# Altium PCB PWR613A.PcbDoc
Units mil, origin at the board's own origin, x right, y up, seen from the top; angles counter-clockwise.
Board outline 2500 x 1850 mil, 2 copper layers (Top Layer, Bottom Layer), stack 64.8 mil thick; 109 components, 70 nets, 324 pads, 62 vias.
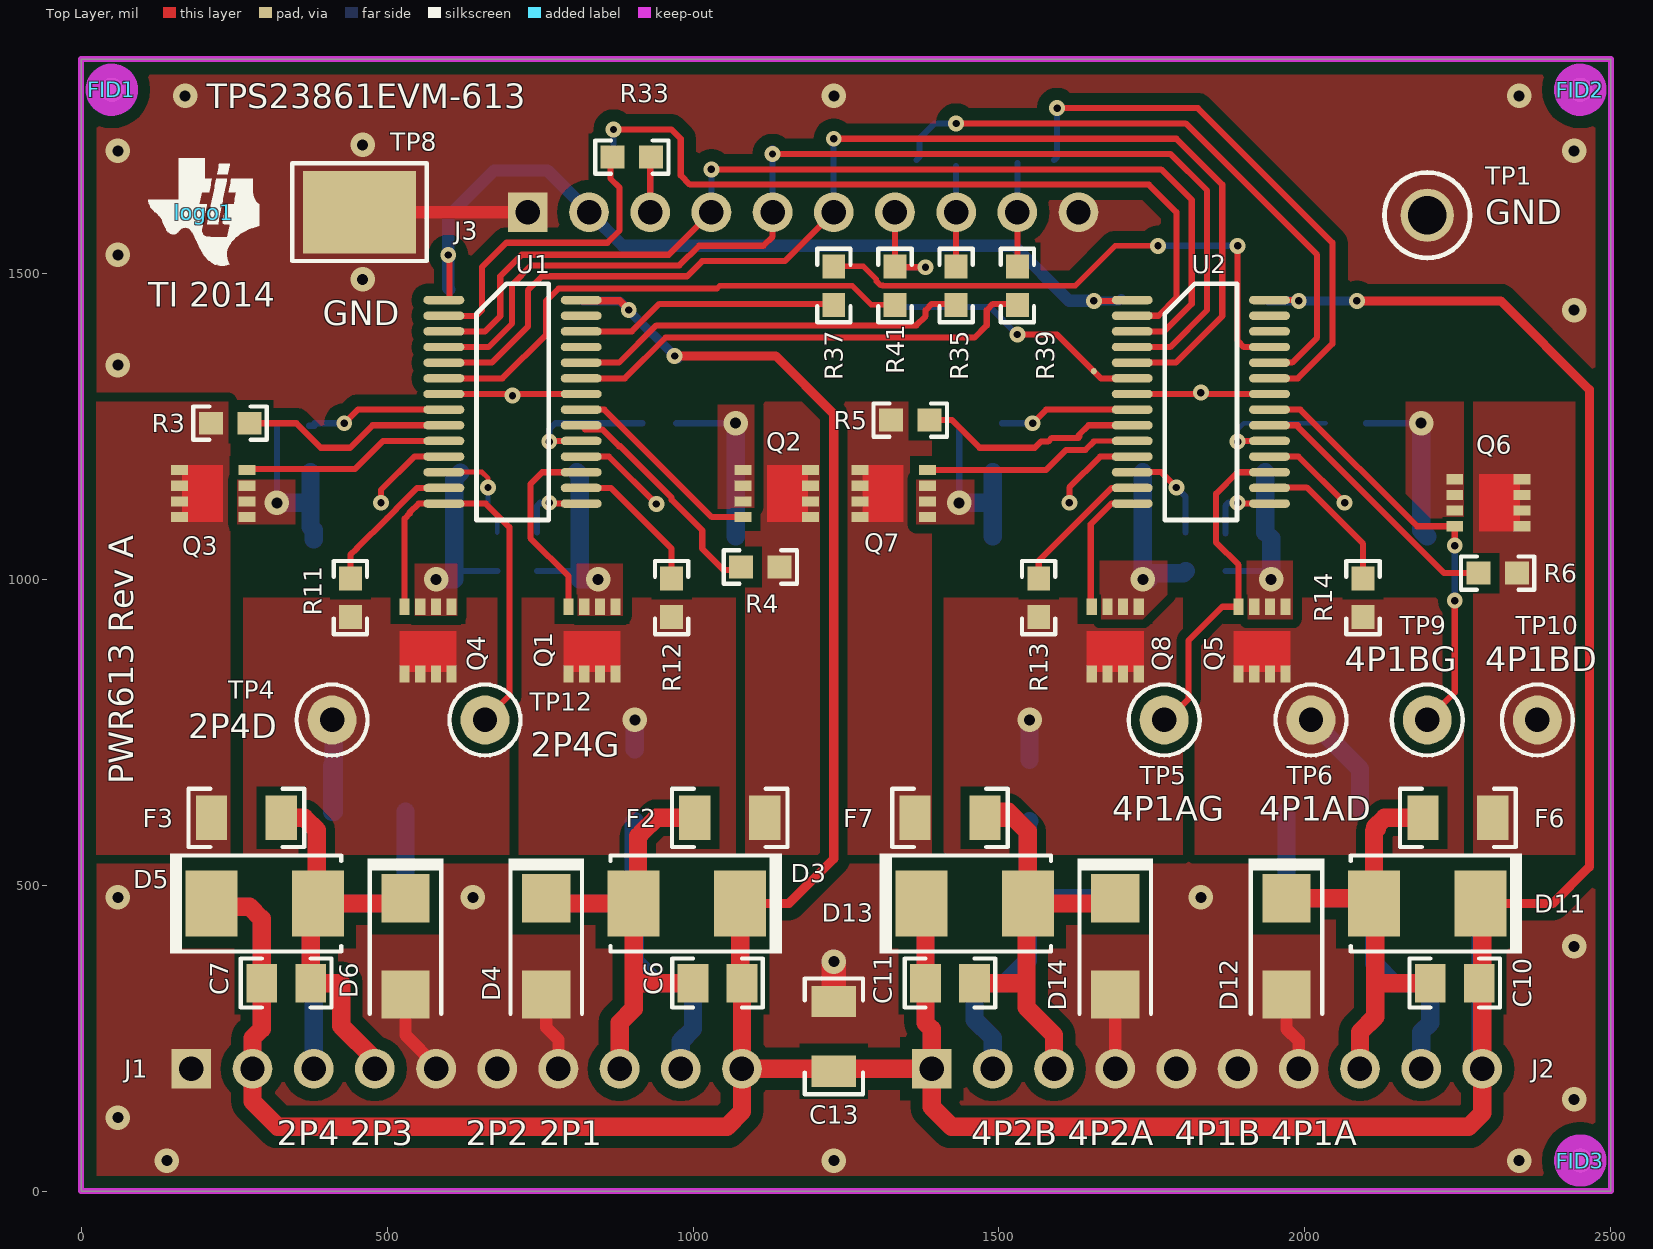
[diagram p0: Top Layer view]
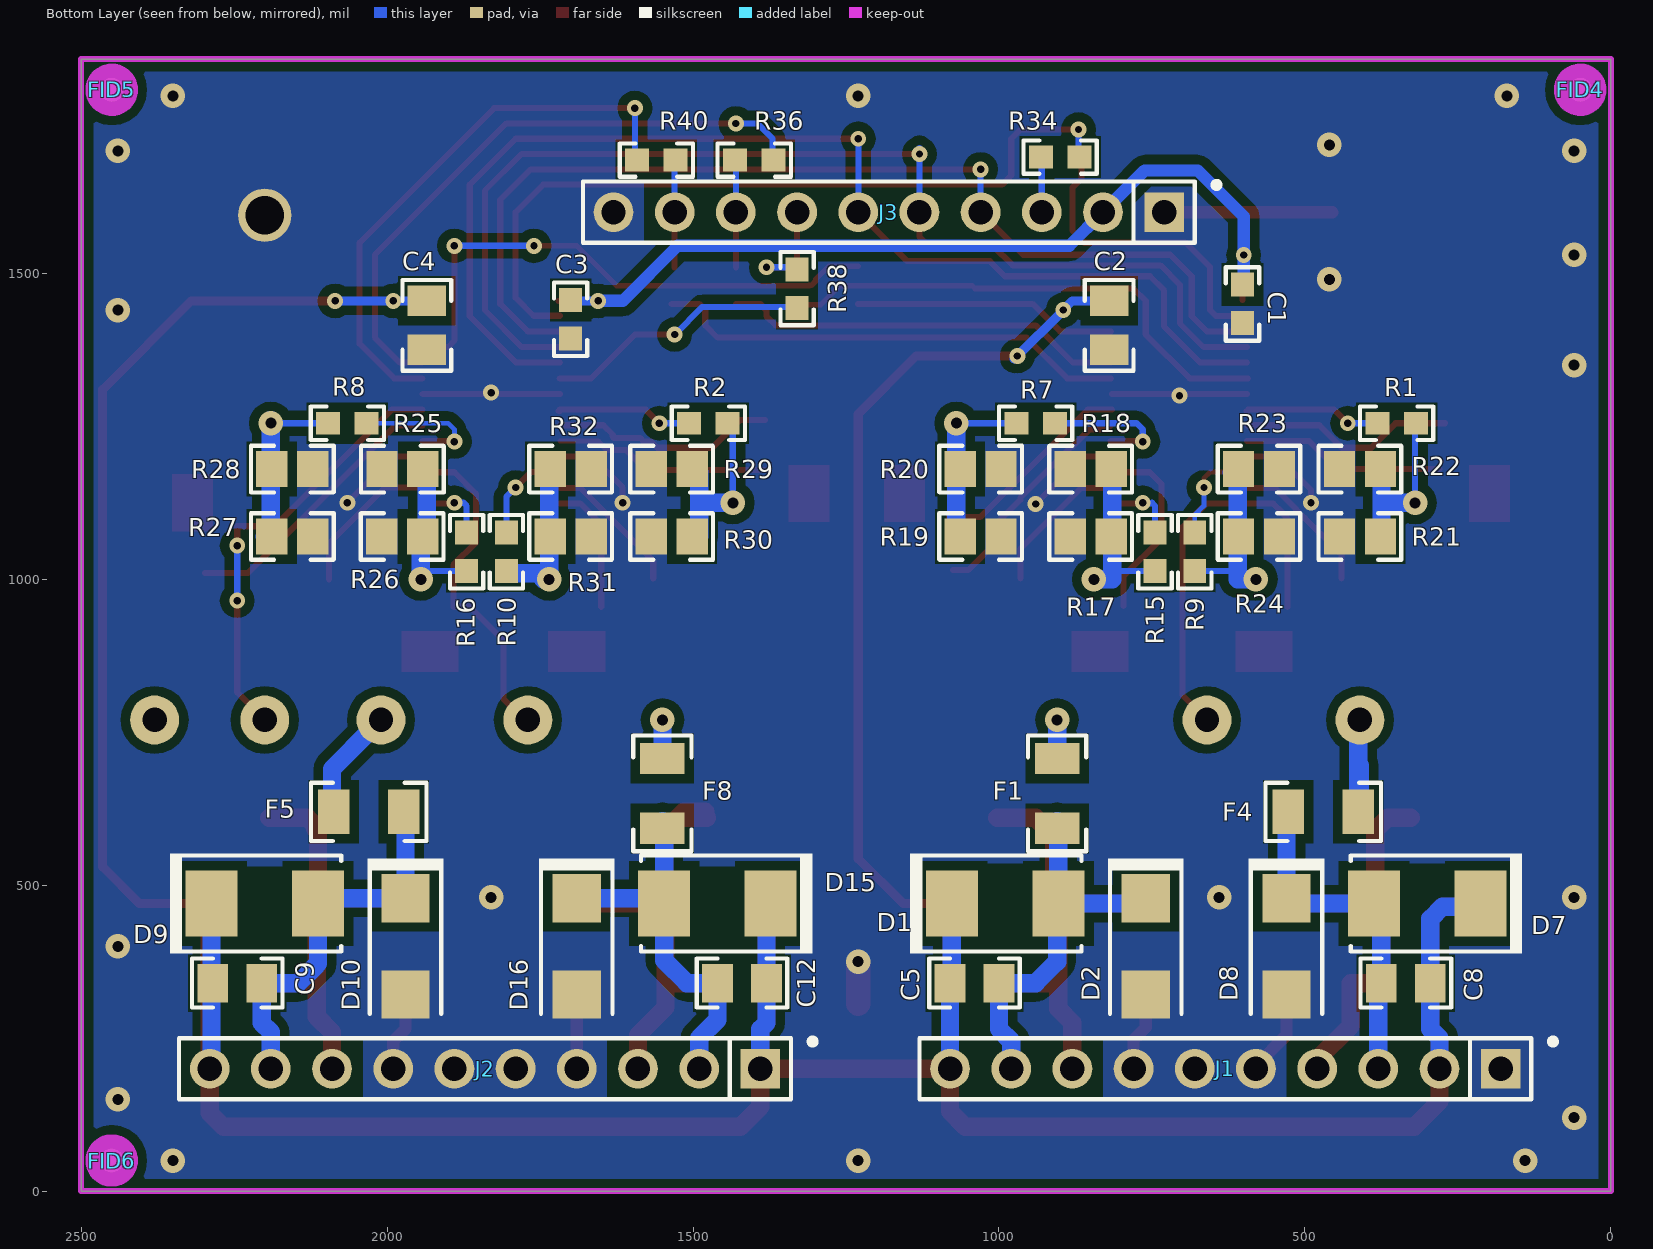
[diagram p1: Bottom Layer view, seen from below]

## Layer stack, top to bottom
Top Layer: signal copper 2.8
Dielectric: core 59.2, FR-4, Dk 4.8
Bottom Layer: signal copper 2.8

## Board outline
0,0 0,1850 2500,1850 2500,0 0,0

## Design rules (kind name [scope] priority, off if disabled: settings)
AcuteAngle [All] p1: minimum=4.50000000000000E+0001 checktracksonly=FALSE
AssemblyTestPointUsage [All] p1: valid=2
Clearance Clearance_19 [InNamedPolygon('PSE-D4')] p1: gap=15
Clearance Clearance_18 [InNamedPolygon('PSE-D7')] p2: gap=15
Clearance Clearance_17 [InNamedPolygon('PSE-D6')] p3: gap=15
Clearance Clearance_16 [InNamedPolygon('PSE-D5')] p4: gap=15
Clearance Clearance_13 [InNamedPolygon('PSE-D1')] p5: gap=15
Clearance Clearance_12 [InNamedPolygon('PSE-D0')] p6: gap=15
Clearance Clearance_11 [InNamedPolygon('PSE-D3')] p7: gap=15
Clearance Clearance_10 [InNamedPolygon('PSE-D2')] p8: gap=15
Clearance Clearance_1 [InNamedPolygon('GND-Bottom')] p9: gap=15
Clearance Clearance_2 [InNamedPolygon('GND-Top')] p10: gap=20
Clearance Clearance_BoardEdge_MountingHoles [OnCopper and InComponentClass('Mounting Holes') vs IsKeepOut] p11: gap=40
Clearance Clearance_BoardEdge_Poly [OnCopper and InPoly vs IsKeepOut] p12: gap=15
Clearance Clearance_BoardEdge [OnCopper and InPoly vs IsKeepOut] p13: gap=25
Clearance [All] p14: gap=7
ComponentClearance ComponentClearance_Logo [All] p1: gap=0 collisioncheckmode=3 verticalgap=10 showdistances=FALSE
ComponentClearance ComponentClearance_ScrewToNut [(HasFootprint('NY PMS 440 0025 PH')) vs (HasFootprint('Keystone_1902C'))] p2: gap=5 collisioncheckmode=3 verticalgap=10 showdistances=FALSE
ComponentClearance ComponentClearance_MountingHoles [InComponentClass('Mounting Holes')] p3: gap=250 collisioncheckmode=3 verticalgap=100000 showdistances=FALSE
ComponentClearance ComponentClearance_SmallPassives [HasFootprint('0201*') or HasFootprint('0402*') or HasFootprint('0508') or HasFootprint('0603*') or HasFootprint('0612') or HasFootprint('0805*') or HasFootprint('0815*') or HasFootprint('0830*') or HasFootprint('1206*') or HasFootprint('1210*') or HasFootprint('1808*') or HasFootprint('1812*') or HasFootprint('1825*') or HasFootprint('2010*') or HasFootprint('2220*') or HasFootprint('2225*') or HasFootprint('2512*') or HasFootprint('2728*') or HasFootprint('3518*') vs HasFootprint('0201*') or HasFootprint('0402*') or HasFootprint('0508') or HasFootprint('0603*') or HasFootprint('0612') or HasFootprint('0805*') or HasFootprint('0815*') or HasFootprint('0830*') or HasFootprint('1206*') or HasFootprint('1210*') or HasFootprint('1808*') or HasFootprint('1812*') or HasFootprint('1825*') or HasFootprint('2010*') or HasFootprint('2220*') or HasFootprint('2225*') or HasFootprint('2512*') or HasFootprint('2728*') or HasFootprint('3518*')] p4: gap=10 collisioncheckmode=3 verticalgap=10 showdistances=FALSE
ComponentClearance ComponentClearance_THtoSMT [IsThruComponent vs IsSMTComponent] p5: gap=10 collisioncheckmode=3 verticalgap=100000 showdistances=FALSE
ComponentClearance ComponentClearance_THtoTH [IsThruComponent vs IsThruComponent] p6: gap=80 collisioncheckmode=3 verticalgap=100000 showdistances=FALSE
ComponentClearance [All] p7: gap=10 collisioncheckmode=3 verticalgap=10 showdistances=FALSE
DiffPairsRouting [All] p1: maxlimit=100 minlimit=10 mostfreqgap=10 maxuncoupledlength=1000
FabricationTestPointUsage TestPointUsage [All] p1: valid=2 allowmultiple=FALSE
FabricationTestpoint Testpoint [All] p1: side=3 testpointundercomponent=TRUE minsize=40 maxsize=100 preferedsize=60 minholesize=0 maxholesize=40 preferedholesize=32 testpointgrid=1 allowsidetop=TRUE allowsidebottom=TRUE usegrid=TRUE gridtolerance=0.01
FanoutControl Fanout_LCC [IsLCC] p1: bgadir=Out bgaviamode=Centered fanoutstyle=Auto fanoutdirection=Alternating viagrid=1 // Fanout_LCC (Default Rule)
FanoutControl Fanout_BGA [IsBGA] p2: bgadir=Out bgaviamode=Centered fanoutstyle=Auto fanoutdirection=Alternating viagrid=1 // Fanout_BGA (Default Rule)
FanoutControl Fanout_Default [All] p4: bgadir=Out bgaviamode=Centered fanoutstyle=Auto fanoutdirection=Alternating viagrid=1 // Fanout_Default (Default Rule)
FanoutControl Fanout_Small [(CompPinCount < 5)] p5: bgadir=Out bgaviamode=Centered fanoutstyle=Auto fanoutdirection=OutThenIn viagrid=1 // Fanout_Small (Default Rule)
HoleSize [All] p1: absolutevalues=TRUE maxlimit=251 minlimit=7 maxpercent=80.000 minpercent=20.000
MinimumAnnularRing [All] p1: minimumring=5
MinimumSolderMaskSliver MinimumSolderMaskSliver_Logo [InComponentClass('Logo') vs InComponentClass('Logo')] p1: minsoldermaskwidth=0.7
MinimumSolderMaskSliver [All] p2: minsoldermaskwidth=4
PlaneConnect [All] p1: planeconnectstyle=Direct reliefexpansion=10 reliefentries=4 reliefconductorwidth=10 reliefairgap=10
PolygonConnect [All] p1: connectstyle=Direct reliefconductorwidth=10 reliefentries=4 polygonreliefangle="90 Angle" airgapwidth=10
RoutingVias [All] p1: holewidth=16 width=34 viastyle="Through Hole" minholewidth=7 minwidth=18 maxholewidth=40 maxwidth=65
SMDToCorner [All] p1: distance=20000
SilkToSilkClearance [All] p1: silktosilkclearance=5
SilkscreenOverComponentPads [All] p1: minsilkscreentomaskgap=5
SolderMaskExpansion [All] p1: expansion=3
Width [All] p1: maxlimit=100 minlimit=6 preferedwidth=10 checkconnectedcopper=TRUE
14 further rules are at their usual default settings.

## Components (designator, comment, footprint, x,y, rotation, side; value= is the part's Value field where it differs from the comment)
C1 "06035C104KAT2A" 0603 602,1450 r270 bottom
C2 "C2012X7R2A104K" 0805_HV 820,1415 r270 bottom
C3 "06035C104KAT2A" 0603 1700,1425 r270 bottom
C4 "C2012X7R2A104K" 0805_HV 1935,1415 r270 bottom
C5 "C2012X7R2A104K" 0805_HV 1040,340 r180 bottom
C6 "C2012X7R2A104K" 0805_HV 1040,340 r180 top
C7 "C2012X7R2A104K" 0805_HV 335,340 r0 top
C8 "C2012X7R2A104K" 0805_HV 335,340 r0 bottom
C9 "C2012X7R2A104K" 0805_HV 2245,340 r180 bottom
C10 "C2012X7R2A104K" 0805_HV 2245,340 r180 top
C11 "C2012X7R2A104K" 0805_HV 1420,340 r0 top
C12 "C2012X7R2A104K" 0805_HV 1420,340 r0 bottom
C13 "GRM31CR72A105KA01L" 1206 1230,252.83 r90 top
D1 "SMBJ58A-13-F" SMB 990,470 r180 bottom
D2 "10MQ100NTRPBF" SMA 760,400 r270 bottom
D3 "SMBJ58A-13-F" SMB 990,470 r180 top
D4 "10MQ100NTRPBF" SMA 760,400 r270 top
D5 "SMBJ58A-13-F" SMB 300,469.98 r0 top
D6 "10MQ100NTRPBF" SMA 530,399.98 r270 top
D7 "SMBJ58A-13-F" SMB 300,469.98 r0 bottom
D8 "10MQ100NTRPBF" SMA 530,399.98 r270 bottom
D9 "SMBJ58A-13-F" SMB 2200,470 r180 bottom
D10 "10MQ100NTRPBF" SMA 1969.99,399.99 r270 bottom
D11 "SMBJ58A-13-F" SMB 2200,470 r180 top
D12 "10MQ100NTRPBF" SMA 1969.99,399.99 r270 top
D13 "SMBJ58A-13-F" SMB 1460.12,469.98 r0 top
D14 "10MQ100NTRPBF" SMA 1690.12,399.98 r270 top
D15 "SMBJ58A-13-F" SMB 1460.12,469.98 r0 bottom
D16 "10MQ100NTRPBF" SMA 1690.12,399.98 r270 bottom
F1 "C1S 1.5" 1206 905,650 r90 bottom
F2 "C1S 1.5" 1206 1060,610 r0 top
F3 "C1S 1.5" 1206 270,610 r180 top
F4 "C1S 1.5" 1206 470,619.98 r180 bottom
F5 "C1S 1.5" 1206 2030,619.86 r0 bottom
F6 "C1S 1.5" 1206 2250,610 r0 top
F7 "C1S 1.5" 1206 1420,610 r180 top
F8 "C1S 1.5" 1206 1550,650 r90 bottom
FID1 "Fiducial" Fiducial10-20 50,1800 r90 top
FID2 "Fiducial" Fiducial10-20 2450,1800 r90 top
FID3 "Fiducial" Fiducial10-20 2450,50 r90 top
FID4 "Fiducial" Fiducial10-20 50,1800 r90 bottom
FID5 "Fiducial" Fiducial10-20 2450,1800 r90 bottom
FID6 "Fiducial" Fiducial10-20 2450,50 r90 bottom
J1 "2P4 2P3 2P2 2P1" TSW-110-07-G-S 630,200 r0 bottom
J2 "Port8&7&6&5" TSW-110-07-G-S 1840,200 r0 bottom
J3 "TSW-110-07-G-S" TSW-110-07-G-S 1180,1600 r0 bottom
logo1 "Texas Instruments" TI_Symbol_Overlay_Small 200,1600 r0 top (schematic designator Logo1)
Q1 "FDMC3612" TRANS_Fairchild_MLP08T 835,900 r270 top
Q2 "FDMC3612" TRANS_Fairchild_MLP08T 1136.68,1140 r0 top
Q3 "FDMC3612" TRANS_Fairchild_MLP08T 215.92,1140 r180 top
Q4 "FDMC3612" TRANS_Fairchild_MLP08T 567,900 r270 top
Q5 "FDMC3612" TRANS_Fairchild_MLP08T 1930,900 r270 top
Q6 "FDMC3612" TRANS_Fairchild_MLP08T 2300,1125 r0 top
Q7 "FDMC3612" TRANS_Fairchild_MLP08T 1327.95,1140 r180 top
Q8 "FDMC3612" TRANS_Fairchild_MLP08T 1690,900 r270 top
R1 "CRCW060322R1FKEA" 0603 350,1255 r0 bottom
R2 "CRCW060322R1FKEA" 0603 1475,1255 r0 bottom
R3 "CRCW060347R0JNEA" 0603 243.35,1255 r0 top
R4 "CRCW060347R0JNEA" 0603 1110,1020 r0 top
R5 "CRCW060347R0JNEA" 0603 1355,1260 r0 top
R6 "CRCW060347R0JNEA" 0603 2315,1010 r0 top
R7 "CRCW060322R1FKEA" 0603 940,1255 r0 bottom
R8 "CRCW060322R1FKEA" 0603 2065,1255 r0 bottom
R9 "CRCW060322R1FKEA" 0603 680,1045 r90 bottom
R10 "CRCW060322R1FKEA" 0603 1805,1045 r90 bottom
R11 "CRCW060347R0JNEA" 0603 440,970 r90 top
R12 "CRCW060347R0JNEA" 0603 965,970 r270 top
R13 "CRCW060347R0JNEA" 0603 1565,970 r90 top
R14 "CRCW060347R0JNEA" 0603 2095,970 r270 top
R15 "CRCW060322R1FKEA" 0603 745,1045 r270 bottom
R16 "CRCW060322R1FKEA" 0603 1870,1045 r270 bottom
R17 "CRM0805-FX-R510ELF" 0805 850,1070 r180 bottom
R18 "CRM0805-FX-R510ELF" 0805 850,1180 r180 bottom
R19 "CRM0805-FX-R510ELF" 0805 1030,1070 r0 bottom
R20 "CRM0805-FX-R510ELF" 0805 1030,1180 r0 bottom
R21 "CRM0805-FX-R510ELF" 0805 410,1070 r180 bottom
R22 "CRM0805-FX-R510ELF" 0805 410,1180 r180 bottom
R23 "CRM0805-FX-R510ELF" 0805 575,1180 r0 bottom
R24 "CRM0805-FX-R510ELF" 0805 575,1070 r0 bottom
R25 "CRM0805-FX-R510ELF" 0805 1975,1180 r180 bottom
R26 "CRM0805-FX-R510ELF" 0805 1975.34,1070 r180 bottom
R27 "CRM0805-FX-R510ELF" 0805 2155,1070 r0 bottom
R28 "CRM0805-FX-R510ELF" 0805 2155,1180 r0 bottom
R29 "CRM0805-FX-R510ELF" 0805 1535,1180 r180 bottom
R30 "CRM0805-FX-R510ELF" 0805 1535,1070 r180 bottom
R31 "CRM0805-FX-R510ELF" 0805 1700,1070 r0 bottom
R32 "CRM0805-FX-R510ELF" 0805 1700,1180 r0 bottom
R33 "CRCW06030000Z0EA" 0603 900,1690 r180 top
R34 "CRCW06030000Z0EA" 0603 900,1690 r180 bottom
R35 "CRCW06030000Z0EA" 0603 1430,1480 r270 top
R36 "CRCW06030000Z0EA" 0603 1400,1685 r180 bottom
R37 "CRCW06030000Z0EA" 0603 1230,1480 r270 top
R38 "CRCW06030000Z0EA" 0603 1330,1475 r270 bottom
R39 "CRCW06030000Z0EA" 0603 1530,1480 r270 top
R40 "CRCW06030000Z0EA" 0603 1560,1685 r0 bottom
R41 "CRCW06030000Z0EA" 0603 1330,1480 r270 top
TP1 "GND" Keystone5011 2200,1595 r90 top
TP4 "2P4D" Keystone5000 410,770 r90 top
TP5 "4P1AG" Keystone5002 1770,770 r90 top
TP6 "4P1AD" Keystone5000 2010,770 r90 top
TP8 "GND" Testpoint_Keystone_Compact 455,1600 r180 top
TP9 "4P1BG" Keystone5002 2200,770 r90 top
TP10 "4P1BD" Keystone5000 2380,770 r90 top
TP12 "2P4G" Keystone5002 660,770 r0 top
U1 "TPS23861PW" PW0028A_N 705,1290 r0 top
U2 "TPS23861PW" PW0028A_N 1830,1290 r0 top
ZZ1 "These assemblies are ESD sensitive, ESD precautions shall be observed." AssemblyNote 150,2310 r0 top
ZZ2 "These assemblies must be clean and free from flux and all contaminants. Use of no clean flux is not acceptable." AssemblyNote 150,2125 r0 top
ZZ3 "These assemblies must comply with workmanship standards IPC-A-610 Class 2., unless otherwise specified." AssemblyNote 150,1950 r0 top

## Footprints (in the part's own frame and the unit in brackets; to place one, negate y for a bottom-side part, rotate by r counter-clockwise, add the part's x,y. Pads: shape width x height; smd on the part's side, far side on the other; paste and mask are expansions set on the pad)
0603 [mm] "0603 from SM-752 data"
  rect 1x0.95 smd: 1(-0.8,0) 2(0.8,0)
  silkscreen extent -1.52,-0.69 1.52,0.69, body extent -0.87,-0.47 0.87,0.47, height 0.85
0805 [mm] "0805 from SM-752 data"
  rect 1.3x1.5 smd: 1(-0.85,0) 2(0.85,0)
  silkscreen extent -1.72,-0.97 1.72,0.97, body extent -1.1,-0.72 1.1,0.72, height 1.1
0805_HV [mil] "0805 with 30mil clearance between pads"
  rect 50x63 smd: 1(-40,0) 2(40,0)
  silkscreen extent -74,-40 74,40, body extent -43,-29 43,29, height 43
1206 [mm] "1206 from SM-752 data"
  rect 1.3x1.85 smd: 1(-1.45,0) 2(1.45,0)
  silkscreen extent -2.4,-1.21 2.4,1.21, body extent -1.7,-0.9 1.7,0.9, height 1.35
AssemblyNote [mil] "Assembly Note"
Fiducial10-20 [mm]
  round 1 smd paste-0.5 mask+0.5: 1(0,0)
  Top Layer keep-out circle w1.178: c0,0 r0.5
Keystone5000 [mil] "For Keystone 500x miniature loop terminals"
  round 80 hole 40: 1(0,0)
  silkscreen extent -58,-58 58,58, body extent -49,-49 49,49, height 182
Keystone5002 [mil] "For Keystone 500x miniature loop terminals"
  round 80 hole 40: 1(0,0)
  silkscreen extent -58,-58 58,58, body extent -49,-49 49,49, height 182
Keystone5011 [mil] "Keystone Multipurpose loops"
  round 87 hole 63: 1(0,0)
  silkscreen extent -70,-70 70,70, body extent -63,-63 63,62, height 319
PW0028A_N [mm] "TSOP, 28-Leads, Body 9.7x4.4mm, Pitch 0.65mm, IPC Medium Density"
  oval 1.7x0.35 smd: 1(-2.85,4.225) 2(-2.85,3.575) 3(-2.85,2.925) 4(-2.85,2.275) 5(-2.85,1.625) 6(-2.85,0.975) 7(-2.85,0.325) 8(-2.85,-0.325) 9(-2.85,-0.975) 10(-2.85,-1.625) 11(-2.85,-2.275) 12(-2.85,-2.925) 13(-2.85,-3.575) 14(-2.85,-4.225) 15(2.85,-4.225) 16(2.85,-3.575) 17(2.85,-2.925) 18(2.85,-2.275) 19(2.85,-1.625) 20(2.85,-0.975) 21(2.85,-0.325) 22(2.85,0.325) 23(2.85,0.975) 24(2.85,1.625) 25(2.85,2.275) 26(2.85,2.925) 27(2.85,3.575) 28(2.85,4.225)
  silkscreen extent -1.5,-4.9 1.5,4.9, body extent -3.21,-4.85 3.21,4.85, height 0.98
SMA [mm] "Molded Diode, 2-Leads, Body 4.3x2.6mm, IPC Medium Density, based on OnSemi component dimensions and land pattern"
  rect 2x2 smd: 1(-2,0) 2(2,0)
  silkscreen extent -3.66,-1.57 2.79,1.57, body extent -2.6,-1.3 2.6,1.3, height 2.42
SMB [mil] "Molded Diode, 2-Leads, Body 5.4x3.6mm, IPC Medium Density, based on OnSemi component dimensions"
  rect 85x107.99 smd: 1(-87.01,0) 2(87.01,0)
  silkscreen extent -155,-82 125,82, body extent -106,-71 106,71, height 91
Testpoint_Keystone_Compact [mil] "Compact SMT test point"
  rect 185x135 smd: 1(0,0)
  silkscreen extent -110,-80 110,80, body extent -75,-56 75,56, height 91
TI_Symbol_Overlay_Small [mil]
  silkscreen extent -90,-88 91,88
TRANS_Fairchild_MLP08T [mm] "Fairchild MLP08T recommended land pattern"
  rect 0.7x0.42 smd mask+0.051: 1(-1.4,0.975) 2(-1.4,0.325) 3(-1.4,-0.325) 4(-1.4,-0.975) 5(1.4,-0.975) 6(1.4,-0.325) 7(1.4,0.325) 8(1.4,0.975)
  Top Layer region: -0.4,-1.185 1.3,-1.185 1.3,1.185 -0.4,1.185
  body extent -1.72,-1.55 1.72,1.55, height 0.8
TSW-110-07-G-S [mm] "Samtec 100mil, 1x10, 230 mil above insulator"
  rect 1.65x1.65 hole 1.016 mask+0: 1(-11.43,0)
  round 1.65 hole 1.016 mask+0: 2(-8.89,0) 3(-6.35,0) 4(-3.81,0) 5(-1.27,0) 6(1.27,0) 7(3.81,0) 8(6.35,0) 9(8.89,0) 10(11.43,0)
  silkscreen extent -13.72,-1.27 12.7,1.27, body extent -12.7,-1.27 12.7,1.27, height 8.38

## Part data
C1 C3: "CAP, CERM, 0.1uF, 50V, +/-10%, X7R, 0603"
C2 C4 C5 C6 C7 C8 C9 C10 C11 C12: "CAP, CERM, 0.1uF, 100V, +/-10%, X7R, 0805"
C13: "CAP, CERM, 1uF, 100V, +/-10%, X7R, 1206"
D1 D3 D5 D7 D9 D11 D13 D15: "Diode, TVS, Uni, 58V, 600W, SMB"
D2 D4 D6 D8 D10 D12 D14 D16: "Diode, Schottky, 100V, 1.5A, SMA"
F1 F2 F3 F4 F5 F6 F7 F8: "Fuse, 1.5A, 63V, SMD"
FID1 FID2 FID3 FID4 FID5 FID6: "Fiducial mark.  There is nothing to buy or mount."
J1 J2: library part TSW-110-07-G-S, "Header, TH, 100mil, 10x1, Gold plated, 230 mil above insulator"
J3: "Header, TH, 100mil, 10x1, Gold plated, 230 mil above insulator"
logo1: library part TI_Logo, "Texas Instrument Corporate Signature"
Q1 Q2 Q3 Q4 Q5 Q6 Q7 Q8: "MOSFET, N-CH, 100V, 3.3A, 3.3x1x3.3mm"
R1 R2 R7 R8 R9 R10 R15 R16: "RES, 22.1 ohm, 1%, 0.1W, 0603"
R3 R4 R5 R6 R11 R12 R13 R14: "RES, 47 ohm, 5%, 0.1W, 0603"
R17 R18 R19 R20 R21 R22 R23 R24 R25 R26 R27 R28 R29 R30 R31 R32: "RES, 0.51 ohm, 1%, 0.25W, 0805"
R33 R34 R35 R36 R37 R38 R39 R40 R41: "RES, 0 ohm, 5%, 0.1W, 0603"
TP1: library part 5011, "Test Point, Multipurpose, Black, TH"
TP4 TP6 TP10: library part 5000, "Test Point, Miniature, Red, TH"
TP5 TP9 TP12: library part 5002, "Test Point, Miniature, White, TH"
TP8: library part 5016, "Test Point, Compact, SMT"
U1 U2: "QUAD IEEE 802.3at POWER-OVER-ETHERNET PSE CONTROLLER, PW0028A"
ZZ1 ZZ2 ZZ3: library part AssemblyNote

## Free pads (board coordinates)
  round 10 smd far side: EndPad(605,1070)
  round 10 smd: EndPad(1655,1340) StartPad(1717.8,1328.39)
  round 30 smd far side: StartPad(2205,340)

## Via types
v1: diameter 26, hole 12, Top Layer to Bottom Layer, 32 vias
v2: diameter 40, hole 18, Top Layer to Bottom Layer, 30 vias

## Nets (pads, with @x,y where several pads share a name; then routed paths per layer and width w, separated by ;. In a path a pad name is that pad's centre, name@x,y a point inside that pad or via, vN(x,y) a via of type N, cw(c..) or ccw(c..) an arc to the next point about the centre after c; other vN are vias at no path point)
3.3V: C1.1 C3.1 J3.2 U1.1 U2.1 | length 1480.5
  Top Layer w10: v1(600,1530) 600,1522 602,1520 U1.1@602,1456.55 ; v1(1655,1455) U2.1@1720,1455
  Bottom Layer w15: v1(1655,1455) 1695.95,1455 C3.1@1700,1459.05
  Bottom Layer w20: C1.1@602,1473.62 600,1475.62 600,1593 675.09,1668.09 761.91,1668.09 J3.2 885,1545 1525,1545 1615,1455 v1(1655,1455)
\PSE_INT: J3.7 R38.1 R41.1 | length 190
  Top Layer w10: J3.7 R41.1 1330,1510 v1(1380,1510)
  Bottom Layer w10: R38.1@1330,1510 v1(1380,1510)
\PSE_RST: J3.3 R33.1 R34.1 | length 190
  Top Layer w10: J3.3 930,1693.5 R33.1@930,1695
  Bottom Layer w10: J3.3 930,1693.5 R34.1@930,1695
\PSE_SHDN: J3.8 R35.1 R36.1 | length 165
  Top Layer w10: R35.1@1430,1510 R35.1 J3.8
  Bottom Layer w10: J3.8 R36.1@1430,1675
AIN1_NC: U1.25
AOUT1: R37.1 U2.25 | length 905.4
  Top Layer w9: R37.1 1278.5,1511.5 1299.8,1490.2 1299.8,1487.05 1306.54,1480.31 1309.69,1480.31 1310,1480 1625,1480 1690,1545 v1@1750,1545
  Top Layer w10: v1@1895,1545 1890,1540 1890,1390 1900.43,1379.57 U2.25
  Bottom Layer w10: v1(1760,1545) v1(1890,1545)
AOUT2: U2.26
CH1_GATE: Q1.4 U1.17 | length 313.8
  Top Layer w10: Q1.4@796.61,956.61 796.61,1004.88 734.14,1067.35 734.14,1155.44 753.54,1174.84 U1.17@815.24,1174.84
CH1_SEN: Q1.1 Q1.2 Q1.3 R15.2 R17.2 R18.2 | length 277.7
  Bottom Layer w10: R15.2 813.5,1013.5 815,1015
  Bottom Layer w30: R18.2@810,1175.01 815,1170.01 815,1070 815,1015 815,1000 v2(845,1000)
CH2_GATE: Q2.4 U1.21 | length 339.1
  Top Layer w10: U1.21@815.24,1277.2 855.24,1277.2 1030.83,1101.61 Q2.4
CH2_SEN: Q2.1 Q2.2 Q2.3 R7.2 R19.2 R20.2 | length 281.9
  Bottom Layer w10: R7.2@972.56,1255 v2(1069.75,1255)
  Bottom Layer w30: R20.2@1069.75,1175.26 v2(1069.75,1255) ; R19.2@1070,1070 R20.2@1070,1175.01
CH3_GATE: Q3.4 U1.10 | length 333.8
  Top Layer w10: Q3.4@279.99,1180 447.32,1180 493.35,1226.02 U1.10@594.76,1226.02
CH3_SEN: Q3.1 Q3.2 Q3.3 R1.1 R21.2 R22.2 | length 290.2
  Bottom Layer w10: v2(320,1125) R1.1@320,1248.29
  Bottom Layer w30: v2(320,1125) 374.68,1125 ; R22.2@374.68,1175 374.68,1125 ; R21.2@380,1065 380,1080 374.68,1085.32 374.68,1125
CH4_GATE: Q4.4 TP12.1 U1.14 | length 657.9
  Top Layer w10: Q4.4 528.61,1099.22 537,1107.6 537,1109.2 551.46,1123.66 U1.14@594.76,1123.66 ; U1.14@610.99,1123.66 661.34,1123.66 700,1085 700,810 TP12.1
CH4_SEN: pad.EndPad@605,1070 Q4.1 Q4.2 Q4.3 R9.1 R23.2 R24.2 | length 279.3
  Bottom Layer w10: 610,1015 611.5,1013.5 R9.1
  Bottom Layer w30: v2(580,1000) 610,1000 610,1015 610,1065 610,1164.52 R23.2@620,1174.52
CH5_GATE: Q5.4 TP5.1 U2.17 | length 569.8
  Top Layer w10: TP5.1@1760,760 TP5.1 1775,770 1810,805 1810,900 1865.12,955.12 Q5.4 1891.61,1023.39 1855,1060 1855,1140 1889.84,1174.84 U2.17
CH5_SEN: Q5.1 Q5.2 Q5.3 R16.2 R25.2 R26.2 | length 245.9
  Bottom Layer w10: R16.2 1931.5,1013.5 v2(1945,1000)
  Bottom Layer w30: R26.2@1935.34,1076.54 R25.2@1935.34,1175.01 ; v2(1945,1000) R26.2@1945,1066.88
CH6_GATE: Q6.4 TP9.1 U2.21 | length 726.9
  Top Layer w10: U2.21 1992.8,1277.2 2183.39,1086.61 Q6.4 Q6.4@2244.88,1085 ; TP9.1 2245,815 v1(2245,965) ; v1(2245,1055) 2245,1050 Q6.4@2245,1085
  Bottom Layer w10: v1(2245,965) 2245,1050 v1(2245,1055)
CH6_SEN: Q6.1 Q6.2 Q6.3 R8.2 R27.2 R28.2 | length 284.1
  Bottom Layer w10: R8.2@2100,1255 v2(2190,1255)
  Bottom Layer w30: v2@2190,1260 2190,1080 R27.2@2200,1070
CH7_GATE: Q7.4 U2.10 | length 354.5
  Top Layer w8: 1655,1225 1656.02,1226.02 U2.10
  Top Layer w10: Q7.4 1576.67,1178.39 1609.74,1211.45 1641.45,1211.45 1655,1225
CH7_SEN: Q7.1 Q7.2 Q7.3 R2.1 R29.2 R30.2 | length 286.5
  Bottom Layer w10: R2.1@1432.8,1250.61 1435,1248.41 v2(1435,1125)
  Bottom Layer w30: v2(1435,1125) 1489.94,1125 ; R30.2@1490,1070 R29.2@1490,1175
CH8_GATE: Q8.4 U2.14 | length 216.7
  Top Layer w10: Q8.4@1650,955 1650,1090 1683.66,1123.66 U2.14
CH8_SEN: Q8.1 Q8.2 Q8.3 R10.1 R31.2 R32.2 | length 260.2
  Bottom Layer w30: R31.2@1735,1070 R32.2@1735,1175 ; R31.2@1735.12,1069.88 v2(1735.12,1000) ; v2@1745,1000 v2(1735.12,1000) ; R10.1 1801.5,1010 1745.12,1010 v2(1735.12,1000)
GND: C1.2 C2.2 C3.2 C4.2 C13.2 D2.2 D4.2 D6.2 D8.2 D10.2 D12.2 D14.2 D16.2 J1.1 J1.5 J1.6 J1.7 J2.4 J2.5 J2.6 J2.7 J3.1 J3.10 R17.1 R18.1 R19.1 R20.1 R21.1 R22.1 R23.1 R24.1 R25.1 R26.1 R27.1 R28.1 R29.1 R30.1 R31.1 R32.1 TP1.1 TP8.1 U1.7 U1.11 U1.18 U1.22 U2.7 U2.11 U2.18 U2.22 | length 1925.9
  Top Layer w10: v1@495,1125 495,1127.48 490,1132.48 490,1145.95 544.49,1200.43 U1.11@594.76,1200.43 ; U1.7@594.76,1302.8 U1.22@815.24,1302.8 ; U1.18@815.24,1200.43 862.67,1200.43 v1(940,1123.1) ; v1(1615,1125) 1615,1150 1665.43,1200.43 U2.11 ; U2.7 1827.8,1302.8 v1(1830,1305) 1832.2,1302.8 U2.22 ; U2.18 1989.57,1200.43 v1(2065,1125) ; v1@2068.23,1128.23 v1@2070.48,1125.97
  Top Layer w20: TP8.1 J3.1 ; D6.2 530,255 580,205 J1.5 ; D4.2 760,267.5 780,247.5 J1.7 ; J2.4@1690.12,200.12 D14.2 ; D12.2 1969.99,265.13 1990,245.12 J2.7
  Top Layer w40: C13.2@1230,305.98 v2(1230,375)
  other v1: 490,1125 705,1300
  other v2: 140,50 1230,50 2350,50 60,120 2440,150 2440,400 60,480 640,480 1830,480 60,1350 2440,1440 460,1490 60,1530 60,1700 2440,1700 460,1710 170,1790 1230,1790 2350,1790
NetR1_2: R1.2 U1.8 | length 231.6
  Top Layer w10: v1(430,1255) 452.2,1277.2 U1.8 ; U1.8@592.8,1275 U1.8@595,1275
  Bottom Layer w10: R1.2@372.56,1250.85 R1.2@381.5,1250.85 ; R1.2 v1(430,1255)
NetR2_2: R2.2 U2.8 | length 224.2
  Top Layer w10: v1(1555,1255) 1577.2,1277.2 U2.8 ; U2.8@1717.8,1275 U2.8@1720,1275
  Bottom Layer w10: R2.2@1505,1255 R2.2 v1(1555,1255)
NetR3_2: R3.2 U1.9 | length 355.6
  Top Layer w10: R3.2@270.91,1255 351.64,1255 391.64,1215.01 439.54,1215.01 476.15,1251.61 U1.9@594.76,1251.61
NetR4_1: R4.1 U1.20 | length 375.4
  Top Layer w10: U1.20 823.91,1244.91 851.6,1244.91 879.08,1217.43 881.02,1217.43 965,1133.45 965,1130 1015,1080 1015,1050 1050,1015 R4.1@1075,1015
NetR5_2: R5.2 U2.9 | length 370
  Top Layer w10: R5.2@1382.56,1260 1423.41,1260 1468.41,1215 1558.55,1215 1568.55,1225 1580.36,1225 1586.51,1231.15 1629.52,1231.15 1631.69,1233.31 ; 1630,1235 1646.61,1251.61 U2.9
NetR6_1: R6.1 U2.20 | length 457.8
  Top Layer w10: U2.20 1985.95,1251.61 ; 1988.39,1251.61 1985.95,1251.61 ; R6.1@2297.44,1009.99 2227.57,1009.99 1985.95,1251.61
NetR7_1: R7.1 U1.19 | length 229.4
  Top Layer w10: v1(765,1225) 766.02,1226.02 U1.19
  Bottom Layer w10: v1(765,1225) 765,1245 775,1255 R7.1@917.68,1255
NetR8_1: R8.1 U2.19 | length 220.3
  Top Layer w10: v1(1890,1225) 1891.02,1226.02 U2.19
  Bottom Layer w8: v1(1890,1225) 1890,1245 1900,1255 R8.1
NetR9_2: R9.2 U1.12 | length 169.1
  Top Layer w8: U1.12@595,1175 655,1175 665,1165 v1(665,1150)
  Top Layer w10: U1.12@594.76,1174.84 U1.12@595,1174.84
  Bottom Layer w8: v1(665,1150) 665,1120 680,1105 R9.2
NetR10_2: R10.2 U2.12 | length 160.1
  Top Layer w10: U2.12@1720,1175 1765,1175 v1(1790,1150)
  Bottom Layer w10: v1(1790,1150) 1805,1135 R10.2
NetR11_2: R11.2 U1.13 | length 237.1
  Top Layer w10: R11.2 440,1040 450,1050 ; 451.14,1051.14 500,1100 500.36,1100 515,1114.64 515,1115 549.25,1149.25 U1.13@594.76,1149.25
NetR12_1: R12.1 U1.16 | length 239.4
  Top Layer w10: U1.16@815.24,1149.25 865.75,1149.25 965,1050 R12.1
NetR13_2: R13.2 U2.13 | length 230.7
  Top Layer w10: R13.2 1565,1030 1684.25,1149.25 U2.13
NetR14_1: R14.1 U2.16 | length 246
  Top Layer w10: U2.16@1945,1150 2002.86,1150 2095,1057.86 R14.1 R14.1@2095,1000
NetR15_1: R15.1 U1.15 | length 121.2
  Top Layer w10: v1(765,1125) 767.65,1125 768.99,1123.66 U1.15@815.24,1123.66
  Bottom Layer w10: R15.1 745,1120 749.14,1124.14 ; 750,1125 749.14,1124.14 ; v1@768.99,1124.14 749.14,1124.14
NetR16_1: R16.1 U2.15 | length 119.8
  Top Layer w10: v1(1890,1125) 1891.34,1123.66 U2.15
  Bottom Layer w10: R16.1@1870,1075 R16.1 1870,1120 1875,1125 v1(1890,1125)
NetR33_2: R33.2 U1.2 | length 512.3
  Top Layer w10: U1.2@595,1430 645,1430 655,1440 655,1510 695,1550 860,1550 880,1570 880,1640 865,1655 865,1685 R33.2@870,1690
NetR34_2: R34.2 U2.2 | length 1280.4
  Top Layer w10: v1(870,1735) 965,1735 980,1720 980,1660 995,1645 1745,1645 1790,1600 1790,1460 1760.75,1430.75 U2.2
  Bottom Layer w10: R34.2@870,1690 v1(870,1735)
NetR35_2: R35.2 U1.24 | length 658.4
  Top Layer w10: U1.24 878.98,1353.98 940,1415 1365,1415 1380,1430 1380,1440 1390,1450 R35.2@1430,1450
NetR36_2: R36.2 U2.24 | length 1016.3
  Top Layer w10: v1(1430,1745) 1805,1745 2020,1530 2020,1395 1978.98,1353.98 U2.24
  Bottom Layer w10: R36.2@1365,1685 1370,1690 1370,1720 1395,1745 v1(1430,1745)
NetR37_2: R37.2 U1.26 | length 431.4
  Top Layer w10: U1.26 900.16,1405.16 945,1450 R37.2@1230,1450
NetR38_2: pad.EndPad@1655,1340 pad.StartPad@1717.8,1328.39 R38.2 U2.6 | length 436.1
  Top Layer w10: v1(1530,1400) 1595,1400 1655,1340 1656.61,1338.39 1666.61,1328.39 U2.6
  Bottom Layer w10: R38.2@1330,1445 1485,1445 v1(1530,1400)
NetR39_2: R39.2 U1.23 | length 782.8
  Top Layer w10: U1.23 888.39,1328.39 955,1395 1460,1395 1480,1415 1480,1440 1490,1450 R39.2@1535,1450
NetR40_2: R40.2 U2.23 | length 919.4
  Top Layer w10: v1(1595,1770) 1825,1770 2045,1550 2045,1385 1988.39,1328.39 U2.23
  Bottom Layer w10: R40.2@1590,1685 1595,1690 v1(1595,1770)
NetR41_2: R41.2 U1.6 | length 845.5
  Top Layer w9: 1039,1475 1044,1480 1260,1480 1291.5,1448.5 R41.2
  Top Layer w10: U1.6 688.39,1328.39 760,1400 760,1455 780.23,1475.23 851.6,1475.23 851.83,1475 1039,1475
PSE_A3: J3.9 R39.1 R40.1 | length 170
  Top Layer w10: R39.1@1530,1510 R39.1 J3.9
  Bottom Layer w10: J3.9 1530,1678.5 R40.1@1530,1680
PSE_D1: F1.2 Q1.5 Q1.6 Q1.7 Q1.8 R12.2 | length 47.9
  Bottom Layer w30: F1.2@905,722.09 v2(905,770)
PSE_D2: F2.2 Q2.5 Q2.6 Q2.7 Q2.8 R4.2
PSE_D3: F3.2 Q3.5 Q3.6 Q3.7 Q3.8 R3.1
PSE_D4: F4.2 Q4.5 Q4.6 Q4.7 Q4.8 R11.1 TP4.1 | length 226.2
  Bottom Layer w30: F4.2@410,619.98 410,695 ; TP4.1 412.91,767.09 F4.2
PSE_D5: F5.2 Q5.5 Q5.6 Q5.7 Q5.8 R14.2 TP6.1 | length 171.9
  Bottom Layer w30: TP6.1@2025,770 2025,755 2090,690 F5.2@2090,625
PSE_D6: F6.2 Q6.5 Q6.6 Q6.7 Q6.8 R6.2 TP10.1
PSE_D7: F7.2 Q7.5 Q7.6 Q7.7 Q7.8 R5.1
PSE_D8: F8.2 Q8.5 Q8.6 Q8.7 Q8.8 R13.1 | length 65
  Bottom Layer w30: F8.2@1550,705 v2(1550,770)
PSE_N1: C5.2 D1.2 D2.1 F1.1 J1.9 | length 617.9
  Bottom Layer w30: D2.1@768.73,470 D1.2 902.99,602.99 F1.1@905,605 ; D1.2@905,465 905,375 940,340 C5.2 1000,265 980,245 J1.9
PSE_N2: C6.2 D3.2 D4.1 F2.1 J1.8 | length 719.2
  Top Layer w30: D4.1@768.73,470 D3.2@900,470 ; J1.8@885,200 880,205 880,275 902.99,297.99 ; 902.99,302.01 D3.2 D3.2@900,470 ; 905,340 C6.2 ; 910,580 910,480 D3.2@900,470 ; 915,585 940,610 F2.1
PSE_N3: C7.2 D5.2 D6.1 F3.1 J1.4 | length 668.8
  Top Layer w30: F3.1 365,610 385,590 D5.2@385,465 ; D5.2@382.5,467.5 375,460 C7.2 425,340 425,270 480,215 J1.4 ; D5.2 D6.1@521.26,469.98
PSE_N4: C8.2 D7.2 D8.1 F4.1 J1.3 | length 551.7
  Bottom Layer w30: J1.3 380,335 C8.2 375,460 D7.2@385,470 ; D7.2 D8.1@521.27,469.98 ; D8.1 F4.1@530,619.98
PSE_N5: C9.2 D9.2 D10.1 F5.1 J2.9 pad.StartPad@2205,340 | length 622
  Bottom Layer w30: F5.1@1970,619.86 D10.1 D9.2@2104.26,478.73 ; 2112.99,372.01 D9.2 ; 2115,370 2145,340 C9.2 2205,275 2190,260 J2.9
PSE_N6: C10.2 D11.2 D12.1 F6.1 J2.8 | length 715.2
  Top Layer w30: D12.1 D11.2@2104.26,478.73 ; J2.8 2090,260 2115,285 2115,340 ; D11.2@2110,470 2115,465 2115,340 ; D11.2 2112.99,587.99 2117.5,592.5 ; 2115,595 2130,610 F6.1 ; C10.2 2115,340
PSE_N7: C11.2 D13.2 D14.1 F7.1 J2.3 | length 756.3
  Top Layer w30: C11.2 1545,340 ; F7.1 1525,610 ; F7.1@1479.87,620 1515,620 1525,610 ; J2.3 1590,255 1545,300 1545,340 ; D14.1@1681.38,469.98 D13.2@1549.98,469.98 ; 1525,610 1547.13,587.87 D13.2 D13.2@1549.98,469.98 ; 1545,340 1545,465 D13.2@1549.98,469.98
PSE_N8: C12.2 D15.2 D16.1 F8.1 J2.2 | length 620.3
  Bottom Layer w30: C12.2 1460,280 1490,250 J2.2 ; C12.2@1460,345 1465,340 1510,340 1547.13,377.13 D15.2 1547.13,602.13 F8.1@1550,605 ; D15.2@1555.87,478.72 D16.1
PSE_SCL: J3.4 U1.3 U2.3 | length 1685.7
  Top Layer w10: U1.3@594.76,1405.16 660.16,1405.16 685,1430 685,1495.28 720.05,1530.32 960.32,1530.32 J3.4 ; v1(1030,1670) 1765,1670 1815,1620 1815,1450 1770.16,1405.16 U2.3
  Bottom Layer w10: J3.4@1030,1625 v1@1030,1665
PSE_SDAI: J3.5 U1.4 U2.4 | length 1869.3
  Top Layer w10: U1.4@594.76,1379.57 665.69,1379.57 704.15,1418.03 704.15,1481.17 735.8,1512.82 977.82,1512.82 1010,1545 1115,1545 1130,1560 J3.5 ; v1(1130,1695) 1780.49,1695 1840,1635.49 1840,1440 1779.57,1379.57 U2.4
  Bottom Layer w10: J3.5 v1(1130,1695) v1@1130,1705
PSE_SDAO: J3.6 U1.5 U2.5 | length 1961.8
  Top Layer w10: U1.5@594.76,1353.98 671.13,1353.98 730,1412.84 730,1472.14 753.13,1495.28 990.28,1495.28 1015,1520 1150,1520 J3.6 ; v1(1230,1720) 1790,1720 1865,1645 1865,1430 1788.98,1353.98 U2.5
  Bottom Layer w10: J3.6 1229.76,1600.24 1229.76,1725 1230,1724.76 v1(1230,1720)
VPWR: C2.1 C4.1 C5.1 C6.1 C7.1 C8.1 C9.1 C10.1 C11.1 C12.1 C13.1 D1.1 D3.1 D5.1 D7.1 D9.1 D11.1 D13.1 D15.1 J1.2 J1.10 J2.1 J2.10 U1.28 U2.28 | length 7734.4
  Top Layer w10: U1.28@815.24,1456.34 U1.28 U1.28@820,1456.34 ; U2.28 v1@1981.34,1456.34
  Top Layer w12: U1.28@820,1455 880,1455 v1(895,1440)
  Top Layer w15: v1(970,1365) 1135,1365 1230,1270 1230,543.35 1156.66,470 D3.1 ; v1(2085,1455) 2320,1455 2465,1310 2465,530 2405,470 D11.1
  Top Layer w30: D5.1 220.02,469.98 225,465 275,465 295,445 C7.1 295,265 280,250 J1.2 280,146.47 321.47,105 1055,105 1080,130 J1.10 ; C6.1@1077.01,342.99 D3.1 ; C6.1 J1.10 ; D13.1@1375,470 1380,465 C11.1 1380,275 1390,265 J2.1 ; D11.1 2290,467 2290,340 J2.10 2290,127.56 2267.44,105 1422.8,105 1390,137.8 J2.1 ; J1.10 J2.1
  Bottom Layer w15: C2.1 880,1455 v1(895,1440) ; v1@894.49,1439.48 v1@975,1360 ; C4.1@1940,1455 v1(1990,1455) v1(2085,1455)
  Bottom Layer w30: D7.1 215.02,469.98 220,465 275,465 295,445 C8.1 295,265 280,250 J1.2 ; C5.1@1077.01,342.99 D1.1 ; J1.10 C5.1 ; D15.1@1380,470 C12.1 1380,275 1390,265 J2.1 ; D9.1 2287,203 J2.10 ; D9.1@2290,470 D9.1@2290,475
pads on no net: FID1.1 FID2.1 FID3.1 FID4.1 FID5.1 FID6.1 U1.27 U2.27

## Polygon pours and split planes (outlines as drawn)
GND on Top Layer "GND-Top" (solid, remove dead copper, pour order 44): 20,20 20,1830 2480,1830 2480,20
PSE_D2 on Top Layer "PSE-D1" (solid, remove dead copper, pour order 48): 1085,550 1220,550 1220,1290 1085,1290
PSE_D1 on Top Layer "PSE-D0" (solid, remove dead copper, pour order 36): 715,550 1070,550 1070,970 715,970
PSE_D4 on Top Layer "PSE-D3" (solid, remove dead copper, pour order 37): 265,550 265,970 700,970 700,550
PSE_D8 on Top Layer "PSE-D7" (solid, remove dead copper, pour order 39): 1800,550 1415,550 1410,553.75 1410,970 1800,970
PSE_D5 on Top Layer "PSE-D4" (solid, remove dead copper, pour order 38): 2260,550 2260,970 1820,970 1820,550
PSE_D7 on Top Layer "PSE-D6" (solid, remove dead copper, pour order 41): 1390,550 1235,550 1235,1290 1390,1290
CH1_SEN on Top Layer "CH0-SEN" (solid, remove dead copper, pour order 28): 810,940 810,1020 810,1025 885,1025 885,940 810,940
CH4_SEN on Top Layer "CH3-SEN" (solid, remove dead copper, pour order 31): 545,940 615,940 615,1020 615,1025 545,1025 545,940
CH3_SEN on Top Layer "CH2-SEN" (solid, remove dead copper, pour order 30): 255,1163 350,1163 350,1090 255,1090 255,1163
CH2_SEN on Top Layer "CH1-SEN" (solid, remove dead copper, pour order 29): 1100,1115 1100,1285 1040,1285 1040,1115 1100,1115
CH7_SEN on Top Layer "CH6-SEN" (solid, remove dead copper, pour order 34): 1365,1163 1460,1163 1460,1090 1365,1090 1365,1163
CH5_SEN on Top Layer "CH4-SEN" (solid, remove dead copper, pour order 32): 1905,935 1905,1030 1980,1030 1980,935 1905,935
CH6_SEN on Top Layer "CH5-SEN" (solid, remove dead copper, pour order 33): 2260,1100 2260,1290 2165,1290 2165,1140 2205,1100 2260,1100
PSE_D3 on Top Layer "PSE-D2" (solid, remove dead copper, pour order 42): 243.35,1073.41 243.35,1290 25,1290 25,550 243.35,550 243.35,1073.41
CH8_SEN on Top Layer "CH7-SEN" (solid, remove dead copper, pour order 35): 1665,935 1665,1030 1775,1030 1775,975 1735,935 1665,935
PSE_D6 on Top Layer "PSE-D5" (solid, remove dead copper, pour order 20): 2275,550 2455,550 2455,1290 2275,1290
GND on Bottom Layer "GND-Bottom" (solid, remove dead copper, pour order 45): 20,20 20,1830 2480,1830 2480,20

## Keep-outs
Keep-Out Layer:
  the board outline again, w10
  text ".Layer_Name" at 577,-858.49 h60

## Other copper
Top Layer:
  pour cut-out: 640,1320 770,1320 770,1275 640,1275
  pour cut-out: 1765,1360 1895,1360 1895,1280 1765,1280
  pour cut-out: 465,1165 525,1165 525,1095 465,1095
  pour cut-out: 905,1150 975,1150 975,1095 905,1095
  pour cut-out: 2030,1150 2105,1150 2105,1095 2030,1095
  pour cut-out: 1585,1150 1650,1150 1650,1095 1585,1095
  text ".Layer_Name" at 577,-858.49 h60
Bottom Layer:
  pour cut-out: 780,1550 780,1650 1580,1650 1580,1550
  pour cut-out: 2165,530 2235,530 2235,450 2215,430 2215,289.98 2190,289.98 2190,376.42 2185,381.42 2185,428.47 2165,448.47
  pour cut-out: 1425,530 1495,530 1495,455.02 1485,445.02 1485,275 1470,260 1455,260 1455,300 1460,300 1460,376.51 1451.51,385 1451.51,423.5 1425,450.02
  pour cut-out: 955,535 1025,535 1025,447.97 1010,432.97 1010,380 1000,380 1000,280 980,280 980,425 955,450
  pour cut-out: 265,535 335,535 335,380 330,375 330,299.98 335,294.98 335,280 335.13,280 355,260.13 355,233.05 331.95,210 325,210 305,230 305,406.76 265,446.76
  pour cut-out: 230,150 230,250 530,250 530,150
  pour cut-out: 830,150 830,250 1130,250 1130,150
  pour cut-out: 1640,150 1640,250 1340,250 1340,150
  pour cut-out: 2040,150 2040,250 2340,250 2340,150
  text ".Layer_Name" at 577,-858.49 h60

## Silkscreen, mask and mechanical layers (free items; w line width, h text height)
Top Overlay:
  text "TPS23861EVM-613" at 205,1770 h40
  text "TI 2014" at 110,1445 h40
  text "PWR613 Rev A" at 85,665 h40 r90
  text "2P4 2P3     2P2 2P1" at 320,75 h40
  text "4P2B 4P2A  4P1B 4P1A" at 1455,75 h40
  text ".Layer_Name" at 577,-858.49 h60
Bottom Overlay:
  text ".Layer_Name" at 577,-858.49 h60
Top Paste:
  text ".Layer_Name" at 577,-858.49 h60
Bottom Paste:
  text ".Layer_Name" at 577,-858.49 h60
Top Solder:
  text ".Layer_Name" at 577,-858.49 h60
  text ".Layer_Name" at 577,-858.49 h60
Bottom Solder:
  text ".Layer_Name" at 577,-858.49 h60
Drill Guide:
  text ".Layer_Name" at 577,-858.49 h60
M1 Board Outline:
  the board outline again, w10
  text ".Layer_Name" at 577,-858.49 h60
M2 Board Dimensions:
  text ".Layer_Name" at 577,-858.49 h60
M3 3D STEP Top:
  text ".Layer_Name" at 577,-858.49 h60
M4 3D STEP Bottom:
  text ".Layer_Name" at 577,-858.49 h60
M5 Assembly Top:
  lines w10: -292,-930.17 6308,-930.17 ; -292,-726.83 6310,-726.83 ; -292,-523.5 -292,-1133.5 3713,-1133.5 6310,-1133.5 6310,-523.5 -291.5,-523.5 -291.5,-1133.5 1284,-1133.5 ; 2173,-1133.5 2173,-523.5 ; 3440,-726.83 3440,-523.5 ; 4280,-726.83 4280,-523.5 ; 4902,-1140 4902,-937.17
  text "COMPONENTS MARKED 'DNP' SHOULD NOT BE POPULATED." at 1153.5,-318.5 h60
  text "ASSEMBLY VARIANT:" at 1153,-434 h60
  text ".VariantName" at 2189,-434 h60
  text "PCB VIEWED FROM TOP SIDE" at -228.5,-655.67 h60
  text "BOARD #:" at 2248,-655.67 h60
  text ".PRJ_Number" at 2793.5,-655.67 h60
  text "REV:" at 3638,-655.67 h60
  text ".PCB_Rev" at 3929.5,-655.67 h60
  text "SVN REV:" at 4476,-655.67 h60
  text ".VersionControl_RevNumber" at 4982,-655.67 h60
  text "IGNORE ->" at -228.5,-858.49 h60
  text "PLOT NAME =" at -228.5,-1064.34 h60
  text ".plot_File_Name" at 577,-1064.34 h60
  text "GENERATED    :" at 2250,-1064.34 h60
  text ".Print_Date" at 3119.5,-1064.34 h60
  text ".Print_Time" at 3848.5,-1064.34 h60
  text "TEXAS INSTRUMENTS" at 5113,-1064.34 h60
M6 Assembly Bottom:
  lines w10: -292.5,-727.33 6309.5,-727.33 ; -290.5,-930.67 6309.5,-930.67 ; 1115.5,-1140.5 1115.5,-937.67 ; 1737.5,-727.33 1737.5,-524 ; 2577.5,-727.33 2577.5,-524 ; 3844.5,-1134 3844.5,-524 ; 4733.5,-1134 6309,-1134 6309,-524 -292.5,-524 -292.5,-1134 2304.5,-1134 6309.5,-1134 6309.5,-524
  text "COMPONENTS MARKED 'DNP' SHOULD NOT BE POPULATED." at 6102,-318 h60
  text ".VariantName" at 5058,-434 h60
  text "ASSEMBLY VARIANT:" at 6097,-434 h60
  text ".VersionControl_RevNumber" at 1035.5,-656.17 h60
  text "SVN REV:" at 1541.5,-656.17 h60
  text ".PCB_Rev" at 2088,-656.17 h60
  text "REV:" at 2379.5,-656.17 h60
  text ".PRJ_Number" at 3224,-656.17 h60
  text "BOARD #:" at 3769.5,-656.17 h60
  text "PCB VIEWED FROM BOTTOM SIDE" at 6246,-656.17 h60
  text "IGNORE ->" at 2547.85,-858.49 h60
  text "TEXAS INSTRUMENTS" at 904.5,-1064.84 h60
  text ".Print_Time" at 2169,-1064.84 h60
  text ".Print_Date" at 2898,-1064.84 h60
  text "GENERATED    :" at 3767.5,-1064.84 h60
  text ".plot_File_Name" at 5440.5,-1064.84 h60
  text "PLOT NAME =" at 6246,-1064.84 h60
M9 Title Sheet:
  drawing of 57 lines, arcs and shapes, not listed
  text "1" at 739.84,8036.5 h70
  text "2" at 3235.5,8036.5 h70
  text "3" at 5724.84,8036.5 h70
  text "4" at 8231.51,8036.5 h70
  text "5" at 10730.5,8036.5 h70
  text "6" at 13235.5,8036.5 h70
  text "A" at -416.5,6893.5 h70
  text "A" at 14383.5,6893.5 h70
  text "B" at -416.5,4513.5 h70
  text "B" at 14383.5,4513.5 h70
  text "C" at -416.5,2138.5 h70
  text "C" at 14383.5,2138.5 h70
  text "PROJECT TITLE:" at 11343.5,277.5 h45
  text ".PRJ_Title" at 11393.5,144.17 h70
  text "DESIGNED FOR:" at 11343.5,-23.5 h45
  text ".PRJ_Customer" at 11393.5,-163.5 h70
  text "D" at -416.5,-231.5 h70
  text "D" at 14383.5,-231.5 h70
  text "FILE NAME:" at 11343.5,-323.5 h45
  text ".PCB_File_Name_No_Path" at 11393.5,-443.5 h70
  text "Texas Instruments (TI) and/or its licensors do not warrant the accuracy or completeness of this specification" at 6374,-605.34 h45
  text "ENGINEER:" at 11343.5,-613.5 h45
  text "LAYOUT BY:" at 12848.5,-613.5 h45
  text "or any information contained therein. TI and/or its licensors do not warrant that this design will meet" at 6329.01,-718 h45
  text ".PRJ_Engineer" at 11393.5,-768.49 h70
  text ".PCB_Layout" at 12899,-768.49 h70
  text "the specifications, will be suitable for your application or fit for any particular purpose, or will operate in" at 6329.01,-830.67 h45
  text ".Layer_Name" at 577,-858.49 h60
  text "ALTIUM DESIGNER VERSION:" at 12848.5,-923.5 h45
  text "an implementation. TI and/or its licensors do not warrant that the design is production worthy. You should" at 6329.01,-943.33 h45
  text "completely validate and test your design implementation to confirm the system functionality for your application." at 6374,-1056 h45
  text ".print_Scale" at 11393.5,-1056.83 h70
  text ".Application_BuildNumber" at 12899,-1056.83 h70
  text "1" at 739.84,-1263.5 h70
  text "2" at 3235.5,-1263.5 h70
  text "3" at 5724.84,-1263.5 h70
  text "4" at 8231.51,-1263.5 h70
  text "5" at 10730.5,-1263.5 h70
  text "6" at 13235.5,-1263.5 h70
M10 Fab Notes:
  drawing of 217 lines, arcs and shapes, not listed
  text "Layer Stack Up Detail for: PWR613A.PcbDoc" at 11360,7797.03 h68
  text "Layer" at 11360,7697.87 h32
  text "Gerber" at 12377.42,7697.87 h32
  text "Copper" at 12956.51,7697.87 h32
  text "Dielectric" at 13587.86,7697.87 h32
  text "Name" at 11360,7633.87 h32
  text "Document" at 12377.42,7633.87 h32
  text "Thickness" at 12956.51,7633.87 h32
  text "Material" at 13587.86,7633.87 h32
  text "Top Solder Mask" at 11360,7511.51 h45
  text "(.GTS)" at 12377.42,7511.51 h45
  text "Solder Resist" at 13587.86,7511.51 h45
  text "Top Layer" at 11360,7384.64 h45
  text "(.GTL)" at 12377.42,7384.64 h45
  text "2.8mil" at 12956.51,7384.64 h45
  text "FR-4" at 13587.86,7321.2 h45
  text "Bottom Layer" at 11360,7257.76 h45
  text "(.GBL)" at 12377.42,7257.76 h45
  text "2.8mil" at 12956.51,7257.76 h45
  text "Bottom Solder Mask" at 11360,7130.89 h45
  text "(.GBS)" at 12377.42,7130.89 h45
  text "Solder Resist" at 13587.86,7130.89 h45
  text "DESIGN INFORMATION" at 12381.02,6810 h60
  text "(REFER ALSO ARRAY/PANEL PROFILING INFORMATION)" at 12019.46,6648.29 h60
  text "BOARD SIZE" at 11333.46,6644 h60
  text "2500MIL" at 11795.78,6516.18 h60
  text "X" at 12301.46,6516.18 h60
  text "1850MIL" at 12532.78,6516.18 h60
  text "Number of Layers :" at 11736.46,6319 h60
  text "2" at 12831.27,6309 h60
  text "MIN. TRACK WIDTH:" at 11736.46,6180 h60
  text "8" at 12832.7,6180 h60
  text "MIL" at 12987.46,6180 h60
  text "MIN. CLEARANCE:" at 11736.46,6048 h60
  text "8" at 12832.7,6048 h60
  text "MIL" at 12987.46,6048 h60
  text "MIN. VIA PAD SIZE:" at 11736.46,5916 h60
  text "24" at 12802.71,5916 h60
  text "MIL" at 12987.46,5916 h60
  text "0.05mm (2MIL)" at 12431.46,5774.29 h60
  text "MINIMUM ANNULAR RING" at 11407.23,5770 h60
  text "EXTERNAL" at 13139.46,5770 h60
  text "PER" at 11607.23,5652 h60
  text "IPC-D-275 CLASS 2 LEVEL C" at 11827.23,5652 h60
  text "MIL, HOLES" at 13315.46,5539.71 h60
  text "+/-" at 12923,5539 h60
  text "+/-" at 13777,5539 h60
  text "REGISTRATION TOLERANCES:" at 11407.23,5534 h60
  text "METAL" at 12607,5534 h60
  text "5" at 13183.2,5534 h60
  text "3" at 14016.2,5534 h60
  text "MIL" at 14132.46,5534 h60
  text "MATERIAL:" at 11332.46,5324.54 h60
  text "FR-4 High Tg" at 12318.9,5184.21 h60
  text "FR-4" at 11793.46,5175.64 h60
  text "X" at 12165.46,5175.64 h60
  text "OTHER" at 13241.46,5175.64 h60
  text "62 MIL (1.6mm) +/-10%" at 12073.56,5012.92 h60
  text "THICKNESS:" at 11407.23,5008.64 h60
  text "X" at 11945.4,5008.64 h60
  text "OTHER" at 13358.46,5008.64 h60
  text "TOLERANCE:" at 11407.23,4850.64 h60
  text "X" at 12246.53,4850.64 h60
  text "ANSI IPC-6012 TYPE 3 CLASS 2" at 12433.48,4850.64 h60
  text "OTHER +/-" at 12433.46,4694.64 h60
  text "BOW & TWIST:" at 11407.23,4537.64 h60
  text "X" at 12246.53,4537.64 h60
  text "ANSI IPC-6012 TYPE 3 CLASS 2" at 12433.48,4537.64 h60
  text "OTHER +/-" at 12433.46,4379.13 h60
  text "COPPER THICKNESS (FINISHED):" at 11332.46,4243.64 h60
  text "1.4MIL (1oz)" at 12212.46,4090.92 h60
  text "2MIL (1.4oz)" at 12979.46,4090.92 h60
  text "X" at 13590,4090.92 h60
  text "2.8MIL (2oz)" at 13706.46,4090.92 h60
  text "OUTER:" at 11689.46,4086.64 h60
  text "1.4MIL (1oz)" at 12212.46,3933.92 h60
  text "2.8MIL (2oz)" at 12979.46,3933.92 h60
  text "N/A" at 13706,3934.29 h60
  text "INNER SIGNAL:" at 11400.38,3929.64 h60
  text "DRILLING:" at 11332.46,3790.64 h60
  text "REFERENCE:" at 11407.23,3673.64 h60
  text "X" at 12055.46,3673.64 h60
  text "AS SHOWN" at 12242.46,3673.64 h60
  text "X" at 12956.46,3673.64 h60
  text "NC_DRILL FILES" at 13093.46,3673.64 h60
  text "PTH MIN COPPER THICKNESS:" at 11407.23,3515.64 h60
  text "X" at 12757.46,3515.64 h60
  text "1MIL" at 12894.46,3515.64 h60
  text "OTHER" at 13391.46,3515.64 h60
  text "BOARD FINISH:" at 11332.46,3356.64 h60
  text "SILKSCREEN:" at 11487.68,3238.64 h60
  text "X" at 12436.46,3238.64 h60
  text "TOP" at 12562.46,3238.64 h60
  text "X" at 12946.46,3238.64 h60
  text "BOTTOM" at 13073.46,3238.64 h60
  text "SILKSCREEN COLOR:" at 11487.68,3071.64 h60
  text "X" at 12435.42,3071.64 h60
  text "WHITE" at 12562.46,3071.64 h60
  text "OTHER" at 13073.46,3071.64 h60
  text "SOLDER RESIST COLOR:" at 11487.68,2901.64 h60
  text "X" at 12055.42,2742.44 h60
  text "GREEN" at 12182.46,2742.44 h60
  text "BLUE" at 12773.46,2742.44 h60
  text "OTHER" at 13311.46,2742.44 h60
  text "IMMERSION GOLD (ENIG)" at 12393.46,2553.92 h60
  text "SURFACE FINISH:" at 11332.46,2549.64 h60
  text "X" at 12210,2545 h60
  text "IMM. TIN/SILVER OR EQUIV" at 11662,2392.64 h60
  text "OTHER" at 13093.46,2392.64 h60
  text "ARRAY/PANEL:" at 11332.46,2213.64 h60
  text "CUT AND TRIM PER MECH LAYER 1" at 12393.46,2209.35 h60
  text "N.C. ROUTE" at 12393.46,2057.64 h60
  text "X" at 13072.46,2057.64 h60
  text "V. SCORE" at 13259.46,2057.64 h60
  text "CERTIFICATION:" at 11332.46,1920.64 h60
  text "MATERIALS AND WORKMANSHIP FOR ALL PCBS" at 12057.46,1920.64 h60
  text "TO MEET OR EXCEED THE REQUIREMENTS OF:" at 12057.46,1822.64 h60
  text "X" at 11683.96,1686.13 h60
  text "ANSI IPC-A-600F CLASS ->" at 11822.96,1686.13 h60
  text "X" at 13462.02,1686.13 h60
  text "2" at 13580.96,1686.14 h60
  text "1" at 13265.96,1684.64 h60
  text "3" at 13934.96,1684.64 h60
  text "X" at 11686.02,1526.64 h60
  text "UL 94V-0" at 11822.96,1526.64 h60
  text "X" at 12498.02,1526.64 h60
  text "RoHS" at 12634.96,1526.64 h60
  text "OTHER" at 13279.36,1526.64 h60
  text "PER ORDER" at 13676.42,1526.64 h60
  text "ADDITIONAL REQUIREMENTS:" at 11332.46,1385.64 h60
  text "MICROSECTION:" at 11407.23,1270.64 h60
  text "YES" at 12312.96,1270.64 h60
  text "REQUIRED" at 13174.46,1114.49 h60
  text "BARE BOARD ELEC. TEST:" at 11407.23,1111.64 h60
  text "NONE" at 12712.96,1111.64 h60
  text "X" at 13047.46,1111.64 h60
  text "PER ORDER" at 13766.46,1111.64 h60
  text "MANUFACTURER'S ID/LOGO:" at 11407.23,954.64 h60
  text "RAIL" at 12872.96,950.35 h60
  text "X" at 13247.46,950.35 h60
  text "METAL" at 13364.77,950.35 h60
  text "SILK" at 13876.46,950.35 h60
  text ".Layer_Name" at 577,-858.49 h60
M11 Gerber Information:
  lines w10: -292,-930.17 6308,-930.17 ; -292,-726.83 6310,-726.83 ; -292,-523.5 -292,-1133.5 3713,-1133.5 6310,-1133.5 6310,-523.5 -291.5,-523.5 -291.5,-1133.5 1284,-1133.5 ; 2173,-1133.5 2173,-523.5 ; 3440,-726.83 3440,-523.5 ; 4280,-726.83 4280,-523.5 ; 4902,-1140 4902,-937.17
  text "ALL ARTWORK VIEWED FROM TOP SIDE" at -228.5,-655.67 h60
  text "BOARD #:" at 2248,-655.67 h60
  text ".PRJ_Number" at 2793.5,-655.67 h60
  text "REV:" at 3638,-655.67 h60
  text ".PCB_Rev" at 3929.5,-655.67 h60
  text "SVN REV:" at 4476,-655.67 h60
  text ".VersionControl_RevNumber" at 4982,-655.67 h60
  text "LAYER NAME =" at -228.5,-858.49 h60
  text "PLOT NAME =" at -228.5,-1064.34 h60
  text ".plot_File_Name" at 577,-1064.34 h60
  text "GENERATED    :" at 2250,-1064.34 h60
  text ".Print_Date" at 3119.5,-1064.34 h60
  text ".Print_Time" at 3848.5,-1064.34 h60
  text "TEXAS INSTRUMENTS" at 5113,-1064.34 h60
M12 Stackup:
  text ".Layer_Name" at 577,-858.49 h60
M13 Component Bodies Top:
  text ".Layer_Name" at 577,-858.49 h60
M14 Component Bodies Bottom:
  text ".Layer_Name" at 577,-858.49 h60
M15 Courtyards Top:
  text ".Layer_Name" at 577,-858.49 h60
M16 Courtyards Bottom:
  text ".Layer_Name" at 577,-858.49 h60
Drill Drawing:
  text ".legend" at 5672.5,735.5 h60
  text "Drill Table" at 5697.5,550.5 h60
  text ".Layer_Name" at 577,-858.49 h60

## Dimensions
-20,0 to -20,1850 on M2 Board Dimensions
0,-30 to 2500,-60 on M2 Board Dimensions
